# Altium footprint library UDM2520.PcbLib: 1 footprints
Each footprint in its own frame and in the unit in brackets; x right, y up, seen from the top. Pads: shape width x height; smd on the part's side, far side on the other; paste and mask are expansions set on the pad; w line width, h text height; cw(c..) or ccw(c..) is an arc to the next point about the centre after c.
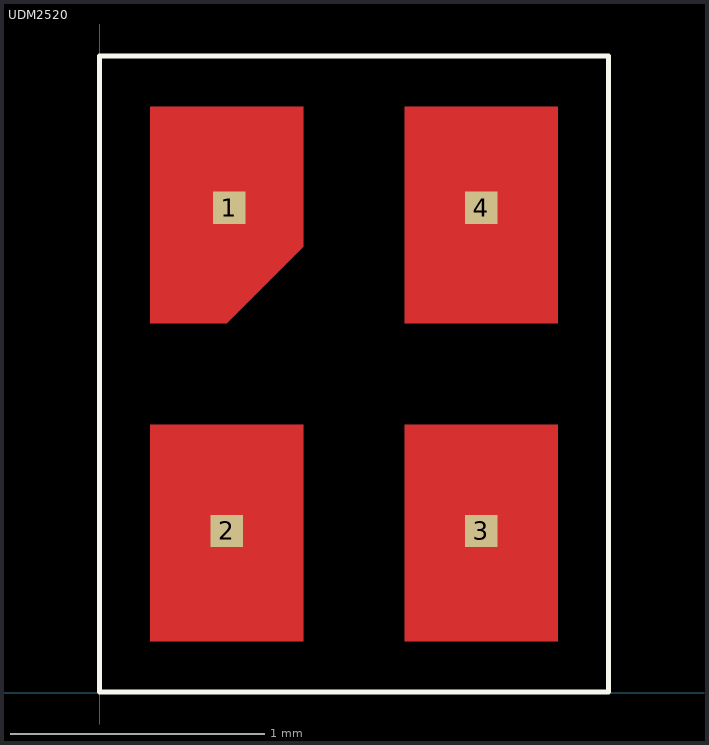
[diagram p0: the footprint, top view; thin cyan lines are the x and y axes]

## UDM2520 [mil]
pads (4):
  rect 5x5 smd mask+0: 1(20,75) 2(19.62,25) 3(58.99,25) 4(58.99,75)
Top Layer:
  region: 7.81,7.94 31.44,7.94 31.44,41.41 7.81,41.41
  region: 47.18,7.94 70.81,7.94 70.81,41.41 47.18,41.41
  region: 47.18,57.15 70.81,57.15 70.81,90.62 47.18,90.62
  region: 7.81,57.15 19.62,57.15 31.44,68.97 31.44,90.62 7.81,90.62
Top Overlay:
  lines w0.79: -0.06,0.07 78.68,0.07 78.68,98.49 -0.06,98.49 -0.06,0.07
Top Paste:
  region: 7.81,7.94 31.44,7.94 31.44,41.41 7.81,41.41
  region: 47.18,7.94 70.81,7.94 70.81,41.41 47.18,41.41
  region: 47.18,57.15 70.81,57.15 70.81,90.62 47.18,90.62
  region: 7.81,57.15 19.62,57.15 31.44,68.97 31.44,90.62 7.81,90.62
Top Solder:
  region: 7.81,7.94 31.44,7.94 31.44,41.41 7.81,41.41
  region: 47.18,7.94 70.81,7.94 70.81,41.41 47.18,41.41
  region: 47.18,57.15 70.81,57.15 70.81,90.62 47.18,90.62
  region: 7.81,57.15 19.62,57.15 31.44,68.97 31.44,90.62 7.81,90.62
3D body: height 47.28, standoff -0.39, extent -0.02,-0.01 78.72,98.41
